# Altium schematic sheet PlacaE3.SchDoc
size A4
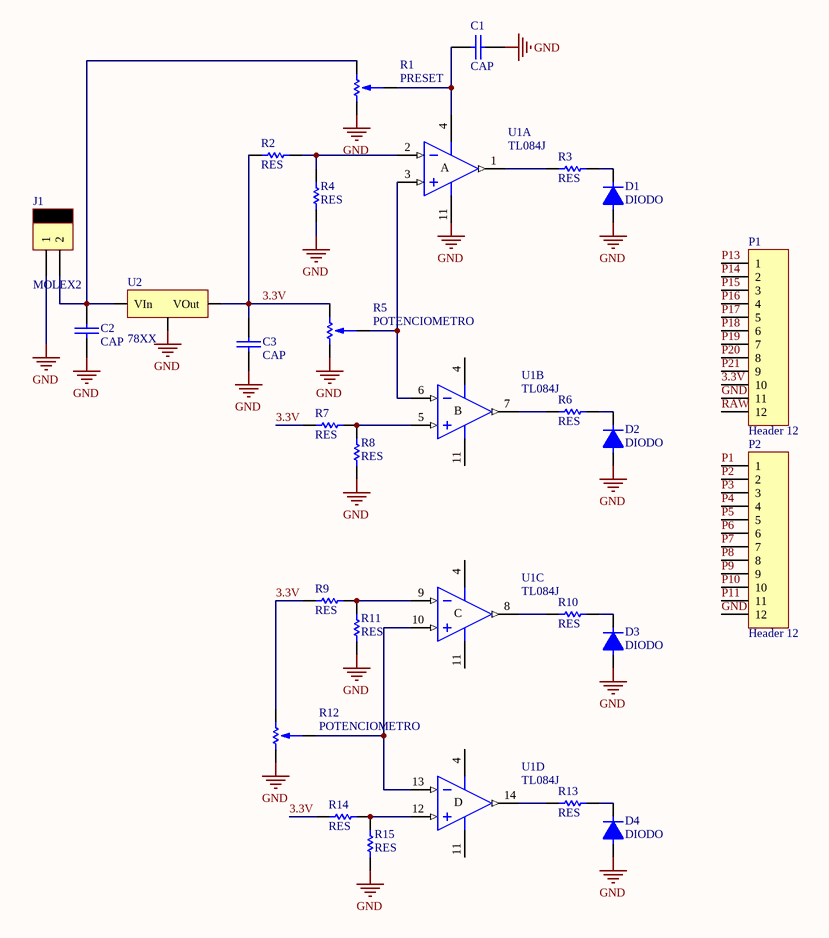
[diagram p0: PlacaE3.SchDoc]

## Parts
C1  CAP  [CAP200]
C2  CAP  [CAP200]
C3  CAP  [CAP200]
D1  DIODO  [DO41]
D2  DIODO  [DO41]
D3  DIODO  [DO41]
D4  DIODO  [DO41]
J1  MOLEX2  [MOLEX2]
P1  Header 12  [HDR1X12]
P2  Header 12  [HDR1X12]
R1  PRESET  [PRESET V]
R2  RES  [RES400]
R3  RES  [RES400]
R4  RES  [RES400]
R5  POTENCIOMETRO  [POTENCIOMETRO]
R6  RES  [RES400]
R7  RES  [RES400]
R8  RES  [RES400]
R9  RES  [RES400]
R10  RES  [RES400]
R11  RES  [RES400]
R12  POTENCIOMETRO  [POTENCIOMETRO]
R13  RES  [RES400]
R14  RES  [RES400]
R15  RES  [RES400]
U1  TL084J  [J014]  (parts A,B,C,D of 4)
U2  78XX  [TO-220 V]

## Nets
GND: C1.2 C2.2 C3.2 D1.1 D2.1 D3.1 D4.1 J1.1 P1.11 P2.12 R1.3 R4.1 R5.3 R8.1 R11.1 R12.3 R15.1 U1.11(V-) U2.2(GND)
3.3V: C3.1 P1.10 R2.1 R5.1 R7.1 R9.1 R12.1 R14.1 U2.3(VOut)
P1: P2.1
P2: P2.2
P3: P2.3
P4: P2.4
P5: P2.5
P6: P2.6
P7: P2.7
P8: P2.8
P9: P2.9
P10: P2.10
P11: P2.11
P13: P1.1
P14: P1.2
P15: P1.3
P16: P1.4
P17: P1.5
P18: P1.6
P19: P1.7
P20: P1.8
P21: P1.9
RAW: P1.12
NetC1_1: C1.1 R1.2 U1.4(V+)
NetC2_1: C2.1 J1.2 R1.1 U2.1(VIn)
NetD1_2: D1.2 R3.2
NetD2_2: D2.2 R6.2
NetD3_2: D3.2 R10.2
NetD4_2: D4.2 R13.2
NetR2_2: R2.2 R4.2 U1.2(IN-)
NetR3_1: R3.1 U1.1(OUT)
NetR5_2: R5.2 U1.3(IN+) U1.6(IN-)
NetR6_1: R6.1 U1.7(OUT)
NetR7_2: R7.2 R8.2 U1.5(IN+)
NetR9_2: R9.2 R11.2 U1.9(IN-)
NetR10_1: R10.1 U1.8(OUT)
NetR12_2: R12.2 U1.10(IN+) U1.13(IN-)
NetR13_1: R13.1 U1.14(OUT)
NetR14_2: R14.2 R15.2 U1.12(IN+)

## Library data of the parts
P1 P2 = Header 12: Header, 12-Pin
U1 = TL084J: JFET-Input Operational Amplifier
U2 = 78XX: REGULDOR POSITIVO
